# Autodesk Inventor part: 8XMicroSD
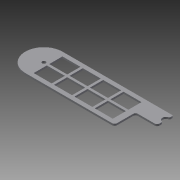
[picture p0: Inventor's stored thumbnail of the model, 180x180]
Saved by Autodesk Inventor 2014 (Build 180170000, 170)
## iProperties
Created: 2015-01
Part Number: 8XMicroSD
Material: Generic
Document SubType Name: Modeling
Designer: Drano
Density: 1 g/cm^3
Appearance: Default
Author: Drano
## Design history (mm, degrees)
sketch "Sketch1"
  geometry: L1 (-34.555, -15.167)-(37.945, -15.167); L2 (-34.555, 15.833)-(56.945, 15.833); L3 (-31.055, -11.667)-(-16.055, -11.667); L4 (-16.055, -11.667)-(-16.055, -0.667); L5 (-31.055, -0.667)-(-16.055, -0.667); L6 (-31.055, -11.667)-(-31.055, -0.667); L7 (-31.055, 1.333)-(-16.055, 1.333); L8 (-16.055, 1.333)-(-16.055, 12.333); L9 (-31.055, 12.333)-(-16.055, 12.333); L10 (-31.055, 1.333)-(-31.055, 12.333); L11 (-14.055, -11.667)-(0.945, -11.667); L12 (0.945, -11.667)-(0.945, -0.667); L13 (-14.055, -0.667)-(0.945, -0.667); L14 (-14.055, -11.667)-(-14.055, -0.667); L15 (-14.055, 1.333)-(0.945, 1.333); L16 (0.945, 1.333)-(0.945, 12.333); L17 (-14.055, 12.333)-(0.945, 12.333); L18 (-14.055, 1.333)-(-14.055, 12.333); L19 (2.945, -11.667)-(17.945, -11.667); L20 (17.945, -11.667)-(17.945, -0.667); L21 (2.945, -0.667)-(17.945, -0.667); L22 (2.945, -11.667)-(2.945, -0.667); L23 (2.945, 1.333)-(17.945, 1.333); L24 (17.945, 1.333)-(17.945, 12.333); L25 (2.945, 12.333)-(17.945, 12.333); L26 (2.945, 1.333)-(2.945, 12.333); L27 (19.945, -11.667)-(34.945, -11.667); L28 (34.945, -11.667)-(34.945, -0.667); L29 (19.945, -0.667)-(34.945, -0.667); L30 (19.945, -11.667)-(19.945, -0.667); L31 (19.945, 1.333)-(34.945, 1.333); L32 (34.945, 1.333)-(34.945, 12.333); L33 (19.945, 12.333)-(34.945, 12.333); L34 (19.945, 1.333)-(19.945, 12.333); L35 (57.945, 4.333)-(57.945, 5.96); L36 (57.945, 13.706)-(57.945, 14.833); L37 (41.945, 2.333)-(55.945, 2.333); L38 (39.945, -13.167)-(39.945, 0.333); C1 r 1.5 at (-34.555, 0.333); A1 r 15.5 centre (-34.555, 0.333) between (-34.555, 15.833) and (-34.555, -15.167); A2 r 2 centre (37.945, -13.167) between (37.945, -15.167) and (39.945, -13.167); A3 r 1 centre (56.945, 14.833) between (57.945, 14.833) and (56.945, 15.833); A4 r 2 centre (55.945, 4.333) between (55.945, 2.333) and (57.945, 4.333); A5 r 3 centre (57.945, 9.833) between (57.195, 12.738) and (57.195, 6.928); A6 r 1 centre (56.945, 5.96) between (57.945, 5.96) and (57.195, 6.928); A7 r 1 centre (56.945, 13.706) between (57.195, 12.738) and (57.945, 13.706); A8 r 2 centre (41.945, 0.333) between (41.945, 2.333) and (39.945, 0.333); 1 further point
  constraints: 76 end point, 16 point on circle, 9 centre point
extrude "Extrusion1" new body sketch "Sketch1" distance "d0" = 1.5; taper "d1" = 0 deg
body "Solid1"
